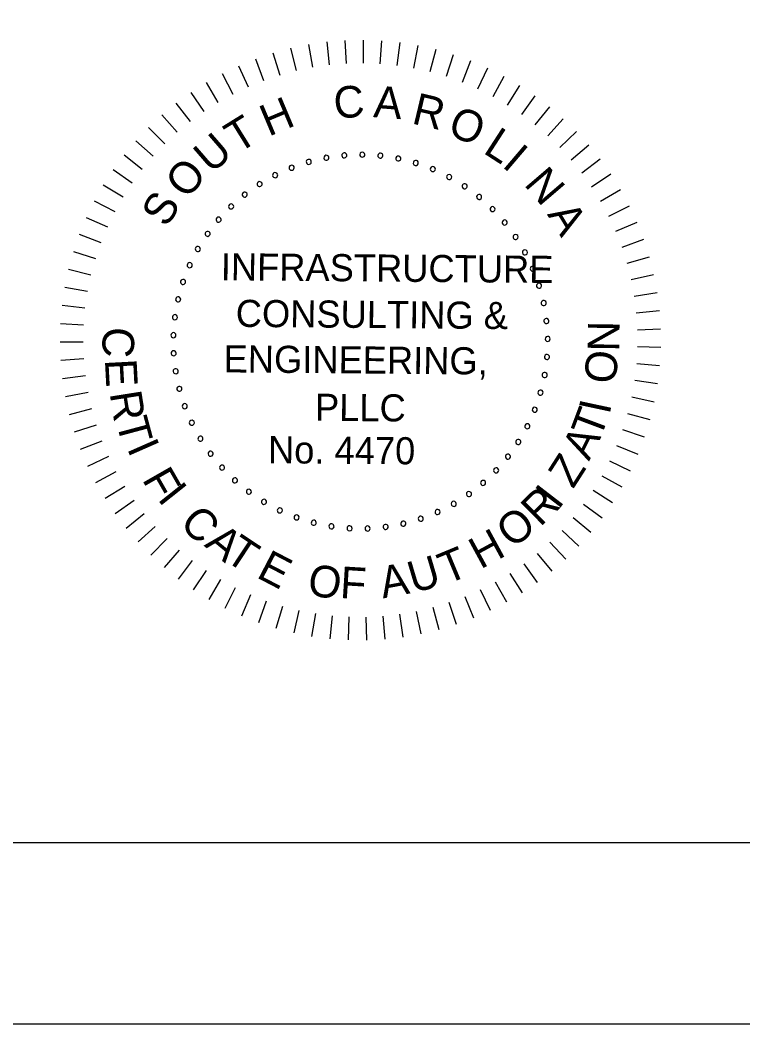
# Model space of a CAD drawing. Extents: x -305 to -161, y -187 to -99.
# Drawn here: x -203.6 to -195.63, y -187.49 to -176.42 of the extents above; entities that cross this region are included whole.
import ezdxf

# ---------------------------------------------------------------- set-up
doc = ezdxf.new("R2010")
doc.units = 0
for name, color, linetype in [('BR_BORDER LINES', 7, 'Continuous'), ('BR_TEXT', 7, 'Continuous'), ('Level 31', 7, 'Continuous')]:
    doc.layers.add(name, color=color, linetype=linetype)

msp = doc.modelspace()

# ---------------------------------------------------------------- linework, layer by layer
at = {"layer": 'BR_BORDER LINES'}
msp.add_line((-297.843, -185.489), (-163.178, -185.489), dxfattribs=at)
at = {"layer": 'BR_TEXT'}
for p, q in [((-200.417, -176.685), (-200.373, -176.936)), ((-200.217, -176.656), (-200.188, -176.909)), ((-200.016, -176.64), (-200.002, -176.894)), ((-199.814, -176.636), (-199.816, -176.89)), ((-199.612, -176.644), (-199.63, -176.898)), ((-199.411, -176.664), (-199.444, -176.917)), ((-199.212, -176.697), (-199.26, -176.947)), ((-200.81, -176.779), (-200.735, -177.023)), ((-200.615, -176.726), (-200.555, -176.974)), ((-199.015, -176.741), (-199.079, -176.988)), ((-198.821, -176.798), (-198.9, -177.04)), ((-201.188, -176.92), (-201.084, -177.153)), ((-201.001, -176.844), (-200.912, -177.082)), ((-198.631, -176.866), (-198.724, -177.103)), ((-198.446, -176.946), (-198.553, -177.177)), ((-201.37, -177.007), (-201.252, -177.233)), ((-198.265, -177.037), (-198.387, -177.261)), ((-201.546, -177.106), (-201.415, -177.324)), ((-198.091, -177.139), (-198.226, -177.355)), ((-201.716, -177.215), (-201.572, -177.425)), ((-197.923, -177.251), (-198.071, -177.458)), ((-201.879, -177.334), (-201.723, -177.535)), ((-197.762, -177.373), (-197.922, -177.571)), ((-202.035, -177.463), (-201.866, -177.654)), ((-202.182, -177.601), (-202.002, -177.781)), ((-197.609, -177.505), (-197.781, -177.693)), ((-197.464, -177.646), (-197.647, -177.823)), ((-202.321, -177.748), (-202.13, -177.917)), ((-197.329, -177.795), (-197.522, -177.961)), ((-202.45, -177.903), (-202.25, -178.06)), ((-197.202, -177.952), (-197.405, -178.106)), ((-202.57, -178.065), (-202.36, -178.21)), ((-197.086, -178.117), (-197.298, -178.258)), ((-202.679, -178.235), (-202.461, -178.366)), ((-196.979, -178.289), (-197.199, -178.417)), ((-202.779, -178.411), (-202.553, -178.529)), ((-196.883, -178.467), (-197.111, -178.581)), ((-202.867, -178.593), (-202.634, -178.696)), ((-196.799, -178.65), (-197.033, -178.75)), ((-202.944, -178.779), (-202.705, -178.869)), ((-196.725, -178.838), (-196.965, -178.924)), ((-203.009, -178.97), (-202.766, -179.045)), ((-196.664, -179.03), (-196.908, -179.101)), ((-203.063, -179.165), (-202.815, -179.225)), ((-196.614, -179.226), (-196.862, -179.282)), ((-203.104, -179.363), (-202.853, -179.407)), ((-196.576, -179.424), (-196.827, -179.465)), ((-203.134, -179.562), (-202.881, -179.592)), ((-196.55, -179.625), (-196.804, -179.65)), ((-203.151, -179.764), (-202.897, -179.777)), ((-196.537, -179.826), (-196.791, -179.836)), ((-203.156, -179.965), (-202.901, -179.964)), ((-196.535, -180.028), (-196.79, -180.022)), ((-203.149, -180.167), (-202.895, -180.15)), ((-196.547, -180.23), (-196.8, -180.208)), ((-203.129, -180.368), (-202.877, -180.335)), ((-196.57, -180.43), (-196.822, -180.393)), ((-203.097, -180.568), (-202.847, -180.52)), ((-196.606, -180.629), (-196.855, -180.577)), ((-203.053, -180.765), (-202.807, -180.701)), ((-196.653, -180.825), (-196.899, -180.758)), ((-202.997, -180.959), (-202.755, -180.881)), ((-196.713, -181.018), (-196.954, -180.936)), ((-202.93, -181.149), (-202.693, -181.056)), ((-196.784, -181.207), (-197.02, -181.111)), ((-202.851, -181.335), (-202.62, -181.228)), ((-196.867, -181.392), (-197.096, -181.281)), ((-202.761, -181.516), (-202.536, -181.395)), ((-196.96, -181.57), (-197.182, -181.446)), ((-202.66, -181.69), (-202.443, -181.556)), ((-197.065, -181.743), (-197.279, -181.605)), ((-202.548, -181.859), (-202.34, -181.711)), ((-197.179, -181.91), (-197.385, -181.759)), ((-202.426, -182.02), (-202.228, -181.86)), ((-197.304, -182.068), (-197.5, -181.905)), ((-202.295, -182.173), (-202.107, -182.002)), ((-202.155, -182.319), (-201.977, -182.136)), ((-197.438, -182.219), (-197.623, -182.045)), ((-197.581, -182.362), (-197.756, -182.176)), ((-202.006, -182.455), (-201.84, -182.262)), ((-197.733, -182.495), (-197.895, -182.3)), ((-201.849, -182.582), (-201.695, -182.379)), ((-197.892, -182.62), (-198.042, -182.414)), ((-201.685, -182.699), (-201.543, -182.487)), ((-201.513, -182.806), (-201.385, -182.586)), ((-198.059, -182.734), (-198.196, -182.519)), ((-201.336, -182.903), (-201.221, -182.675)), ((-198.411, -182.93), (-198.522, -182.701)), ((-198.232, -182.837), (-198.356, -182.615)), ((-201.153, -182.988), (-201.053, -182.754)), ((-198.596, -183.012), (-198.692, -182.777)), ((-200.965, -183.062), (-200.879, -182.822)), ((-200.773, -183.125), (-200.702, -182.88)), ((-198.978, -183.142), (-199.045, -182.896)), ((-198.785, -183.083), (-198.867, -182.842)), ((-200.577, -183.175), (-200.521, -182.927)), ((-200.379, -183.214), (-200.338, -182.962)), ((-200.179, -183.24), (-200.154, -182.987)), ((-199.978, -183.254), (-199.968, -183)), ((-199.776, -183.256), (-199.781, -183.002)), ((-199.574, -183.246), (-199.595, -182.992)), ((-199.373, -183.223), (-199.41, -182.971)), ((-199.174, -183.188), (-199.226, -182.939))]:
    msp.add_line(p, q, dxfattribs=at)
for centre, start, end in [((-200.22, -177.935), 10.6038, 190.6038), ((-200.22, -177.935), 190.6038, 10.6038), ((-200.023, -177.908), 5.0653, 185.0653), ((-200.023, -177.908), 185.0653, 5.0653), ((-199.824, -177.9), 359.5268, 179.5268), ((-199.824, -177.9), 179.5268, 359.5268), ((-199.625, -177.912), 353.9884, 173.9884), ((-199.625, -177.912), 173.9884, 353.9884), ((-199.428, -177.943), 168.4499, 348.4499), ((-199.428, -177.943), 348.4499, 168.4499), ((-200.603, -178.045), 21.6807, 201.6807), ((-200.603, -178.045), 201.6807, 21.6807), ((-200.414, -177.98), 16.1422, 196.1422), ((-200.414, -177.98), 196.1422, 16.1422), ((-199.235, -177.992), 162.9114, 342.9114), ((-199.235, -177.992), 342.9114, 162.9114), ((-199.047, -178.06), 157.373, 337.373), ((-199.047, -178.06), 337.373, 157.373), ((-200.785, -178.127), 27.2191, 207.2191), ((-200.785, -178.127), 207.2191, 27.2191), ((-198.867, -178.146), 151.8345, 331.8345), ((-198.867, -178.146), 331.8345, 151.8345), ((-200.957, -178.226), 32.7576, 212.7576), ((-200.957, -178.226), 212.7576, 32.7576), ((-198.697, -178.249), 146.2961, 326.2961), ((-198.697, -178.249), 326.2961, 146.2961), ((-201.12, -178.341), 38.2961, 218.2961), ((-201.12, -178.341), 218.2961, 38.2961), ((-198.537, -178.368), 140.7576, 320.7576), ((-198.537, -178.368), 320.7576, 140.7576), ((-201.27, -178.472), 43.8345, 223.8345), ((-201.27, -178.472), 223.8345, 43.8345), ((-198.389, -178.502), 135.2191, 315.2191), ((-198.389, -178.502), 315.2191, 135.2191), ((-201.408, -178.617), 49.373, 229.373), ((-201.408, -178.617), 229.373, 49.373), ((-198.255, -178.649), 129.6807, 309.6807), ((-198.255, -178.649), 309.6807, 129.6807), ((-201.53, -178.774), 54.9114, 234.9114), ((-201.53, -178.774), 234.9114, 54.9114), ((-198.135, -178.809), 124.1422, 304.1422), ((-198.135, -178.809), 304.1422, 124.1422), ((-201.637, -178.942), 60.4499, 240.4499), ((-201.637, -178.942), 240.4499, 60.4499), ((-198.032, -178.979), 118.6038, 298.6038), ((-198.032, -178.979), 298.6038, 118.6038), ((-201.727, -179.12), 65.9884, 245.9884), ((-201.727, -179.12), 245.9884, 65.9884), ((-197.945, -179.159), 113.0653, 293.0653), ((-197.945, -179.159), 293.0653, 113.0653), ((-201.8, -179.305), 71.5268, 251.5268), ((-201.8, -179.305), 251.5268, 71.5268), ((-197.876, -179.346), 107.5268, 287.5268), ((-197.876, -179.346), 287.5268, 107.5268), ((-201.854, -179.497), 77.0653, 257.0653), ((-201.854, -179.497), 257.0653, 77.0653), ((-197.826, -179.538), 101.9884, 281.9884), ((-197.826, -179.538), 281.9884, 101.9884), ((-201.89, -179.693), 82.6038, 262.6038), ((-201.89, -179.693), 262.6038, 82.6038), ((-197.795, -179.735), 96.4499, 276.4499), ((-197.795, -179.735), 276.4499, 96.4499), ((-201.906, -179.892), 88.1422, 268.1422), ((-201.906, -179.892), 268.1422, 88.1422), ((-197.782, -179.934), 90.9114, 270.9114), ((-197.782, -179.934), 270.9114, 90.9114), ((-201.904, -180.091), 93.6807, 273.6807), ((-201.904, -180.091), 273.6807, 93.6807), ((-197.789, -180.133), 85.373, 265.373), ((-197.789, -180.133), 265.373, 85.373), ((-201.882, -180.289), 99.2191, 279.2191), ((-201.882, -180.289), 279.2191, 99.2191), ((-197.815, -180.331), 79.8345, 259.8345), ((-197.815, -180.331), 259.8345, 79.8345), ((-201.841, -180.484), 104.7576, 284.7576), ((-201.841, -180.484), 284.7576, 104.7576), ((-197.86, -180.525), 74.2961, 254.2961), ((-197.86, -180.525), 254.2961, 74.2961), ((-201.781, -180.675), 110.2961, 290.2961), ((-201.781, -180.675), 290.2961, 110.2961), ((-197.924, -180.714), 68.7576, 248.7576), ((-197.924, -180.714), 248.7576, 68.7576), ((-201.703, -180.858), 115.8345, 295.8345), ((-201.703, -180.858), 295.8345, 115.8345), ((-198.005, -180.896), 63.2191, 243.2191), ((-198.005, -180.896), 243.2191, 63.2191), ((-201.608, -181.033), 121.373, 301.373), ((-201.608, -181.033), 301.373, 121.373), ((-198.104, -181.069), 57.6807, 237.6807), ((-198.104, -181.069), 237.6807, 57.6807), ((-201.497, -181.199), 126.9114, 306.9114), ((-201.497, -181.199), 306.9114, 126.9114), ((-198.219, -181.232), 52.1422, 232.1422), ((-198.219, -181.232), 232.1422, 52.1422), ((-201.37, -181.352), 132.4499, 312.4499), ((-201.37, -181.352), 312.4499, 132.4499), ((-198.349, -181.383), 46.6038, 226.6038), ((-198.349, -181.383), 226.6038, 46.6038), ((-201.228, -181.493), 137.9884, 317.9884), ((-201.228, -181.493), 317.9884, 137.9884), ((-201.074, -181.619), 323.5268, 143.5268), ((-198.493, -181.521), 41.0653, 221.0653), ((-198.493, -181.521), 221.0653, 41.0653), ((-201.074, -181.619), 143.5268, 323.5268), ((-200.909, -181.73), 329.0653, 149.0653), ((-198.649, -181.644), 35.5268, 215.5268), ((-198.649, -181.644), 215.5268, 35.5268), ((-200.909, -181.73), 149.0653, 329.0653), ((-200.733, -181.825), 154.6038, 334.6038), ((-200.733, -181.825), 334.6038, 154.6038), ((-198.995, -181.842), 24.4499, 204.4499), ((-198.817, -181.752), 29.9884, 209.9884), ((-198.817, -181.752), 209.9884, 29.9884), ((-200.549, -181.902), 160.1422, 340.1422), ((-200.549, -181.902), 340.1422, 160.1422), ((-199.18, -181.916), 18.9114, 198.9114), ((-199.18, -181.916), 198.9114, 18.9114), ((-198.995, -181.842), 204.4499, 24.4499), ((-200.359, -181.961), 165.6807, 345.6807), ((-200.359, -181.961), 345.6807, 165.6807), ((-200.164, -182.001), 171.2191, 351.2191), ((-200.164, -182.001), 351.2191, 171.2191), ((-199.965, -182.022), 176.7576, 356.7576), ((-199.965, -182.022), 356.7576, 176.7576), ((-199.766, -182.024), 2.2961, 182.2961), ((-199.766, -182.024), 182.2961, 2.2961), ((-199.568, -182.007), 7.8345, 187.8345), ((-199.568, -182.007), 187.8345, 7.8345), ((-199.372, -181.971), 13.373, 193.373), ((-199.372, -181.971), 193.373, 13.373)]:
    msp.add_arc(centre, 0.028, start, end, dxfattribs=at)
at = {"layer": 'Level 31'}
msp.add_lwpolyline([(-305.176, -187.489), (-161.176, -187.489), (-161.176, -99.489), (-305.176, -99.489)], close=True, dxfattribs=at)

# ---------------------------------------------------------------- texts
at = {"layer": 'BR_TEXT'}
for s, height, rotation, p in [('C', 0.349, 4.7281, (-200.126, -177.506)), ('A', 0.349, 355.6981, (-199.708, -177.486)), ('H', 0.349, 22.7882, (-200.857, -177.704)), ('R', 0.349, 346.6681, (-199.291, -177.554)), ('O', 0.349, 337.638, (-198.9, -177.673)), ('T', 0.349, 31.8182, (-201.196, -177.894)), ('L', 0.349, 327.108, (-198.504, -177.875)), ('U', 0.349, 40.8482, (-201.49, -178.119)), ('I', 0.349, 319.578, (-198.294, -178.026)), ('O', 0.349, 49.8782, (-201.757, -178.403)), ('N', 0.349, 310.548, (-198.051, -178.23)), ('S', 0.349, 58.9083, (-201.979, -178.715)), ('A', 0.349, 301.5179, (-197.791, -178.559)), ('INFRASTRUCTURE', 0.29909, 359.5268, (-201.385, -179.286)), ('CONSULTING &', 0.29909, 359.5268, (-201.22, -179.8)), ('C', 0.349, 267.025, (-202.679, -179.795)), ('N', 0.349, 89.2085, (-196.993, -180.074)), ('ENGINEERING,', 0.29909, 359.5268, (-201.354, -180.302)), ('O', 0.349, 83.2085, (-197.038, -180.44)), ('E', 0.349, 273.025, (-202.662, -180.161)), ('R', 0.349, 279.025, (-202.61, -180.531)), ('PLLC', 0.2991, 359.5268, (-200.347, -180.836)), ('T', 0.349, 69.3954, (-197.203, -181.047)), ('I', 0.349, 77.9093, (-197.1, -180.777)), ('T', 0.349, 285.025, (-202.541, -180.846)), ('I', 0.349, 293.7713, (-202.422, -181.138)), ('No. 4470', 0.2991, 359.5268, (-200.865, -181.304)), ('A', 0.349, 63.3954, (-197.326, -181.288)), ('Z', 0.349, 57.3954, (-197.501, -181.594)), ('F', 0.349, 299.7713, (-202.257, -181.482)), ('I', 0.349, 308.5268, (-202.089, -181.698)), ('R', 0.349, 44.5268, (-197.863, -182.014)), ('I', 0.349, 52.3339, (-197.665, -181.825)), ('C', 0.349, 314.5268, (-201.851, -181.978)), ('O', 0.349, 38.5268, (-198.169, -182.254)), ('A', 0.349, 320.5268, (-201.575, -182.213)), ('H', 0.349, 28.5268, (-198.522, -182.478)), ('T', 0.349, 326.5268, (-201.357, -182.366)), ('T', 0.349, 22.5268, (-198.894, -182.645)), ('E', 0.349, 332.5268, (-201.003, -182.558)), ('U', 0.349, 16.5268, (-199.261, -182.742)), ('O', 0.349, 350.5268, (-200.442, -182.753)), ('F', 0.349, 356.5268, (-200.076, -182.79)), ('A', 0.349, 10.5268, (-199.597, -182.796))]:
    msp.add_text(s, height=height, rotation=rotation, dxfattribs=at).set_placement(p)

doc.saveas('drawing.dxf')
